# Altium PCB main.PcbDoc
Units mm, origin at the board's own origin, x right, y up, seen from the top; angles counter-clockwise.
Board outline 80 x 80 mm, 2 copper layers (Top, Bottom), stack 0 mm thick; 84 components, 75 nets, 337 pads, 197 vias.
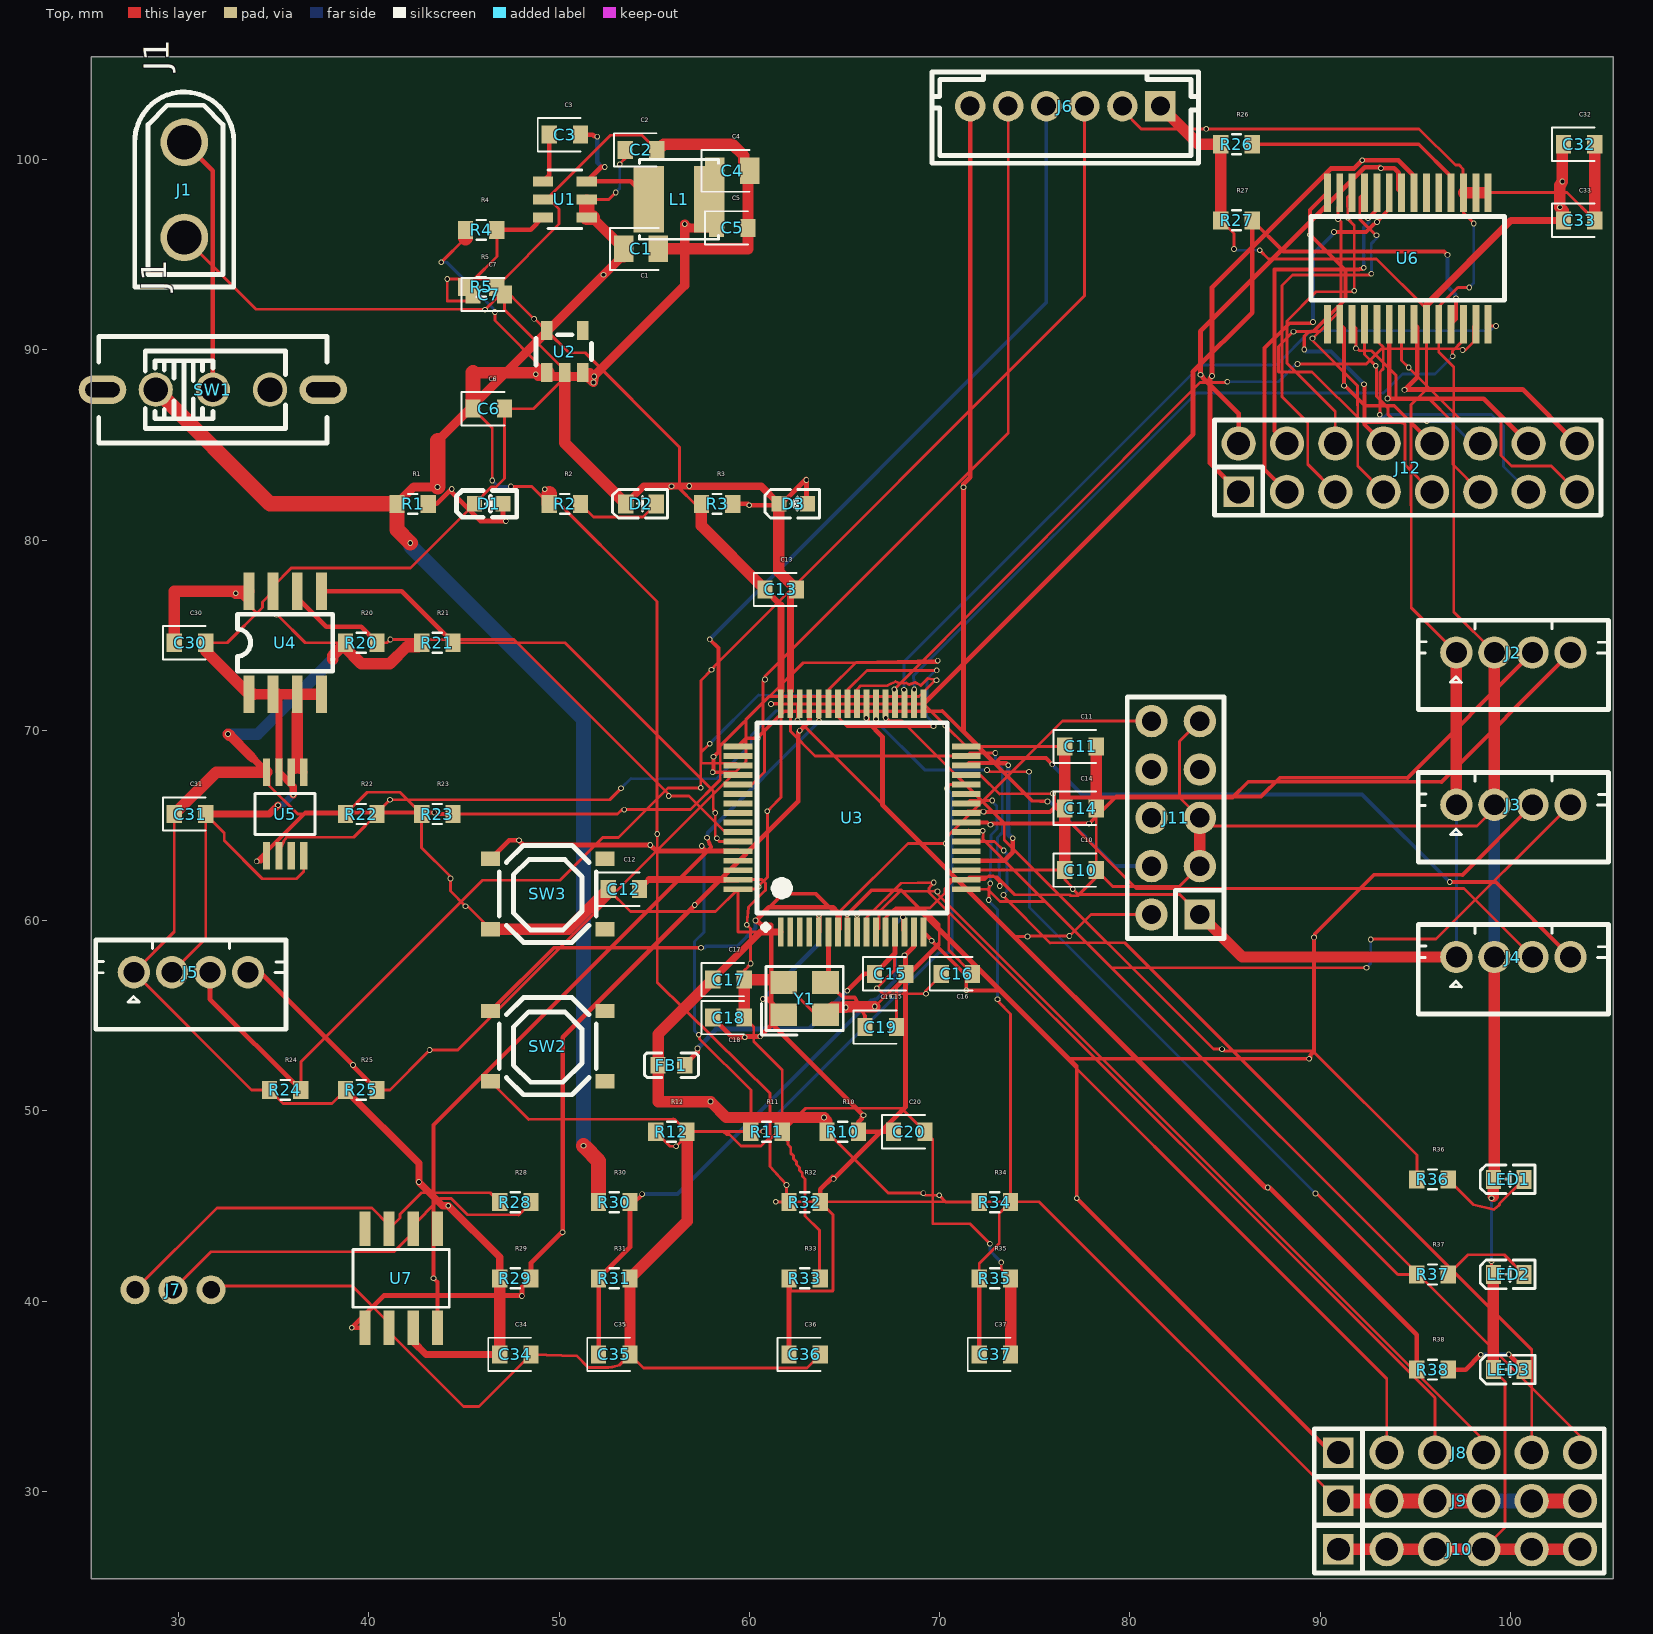
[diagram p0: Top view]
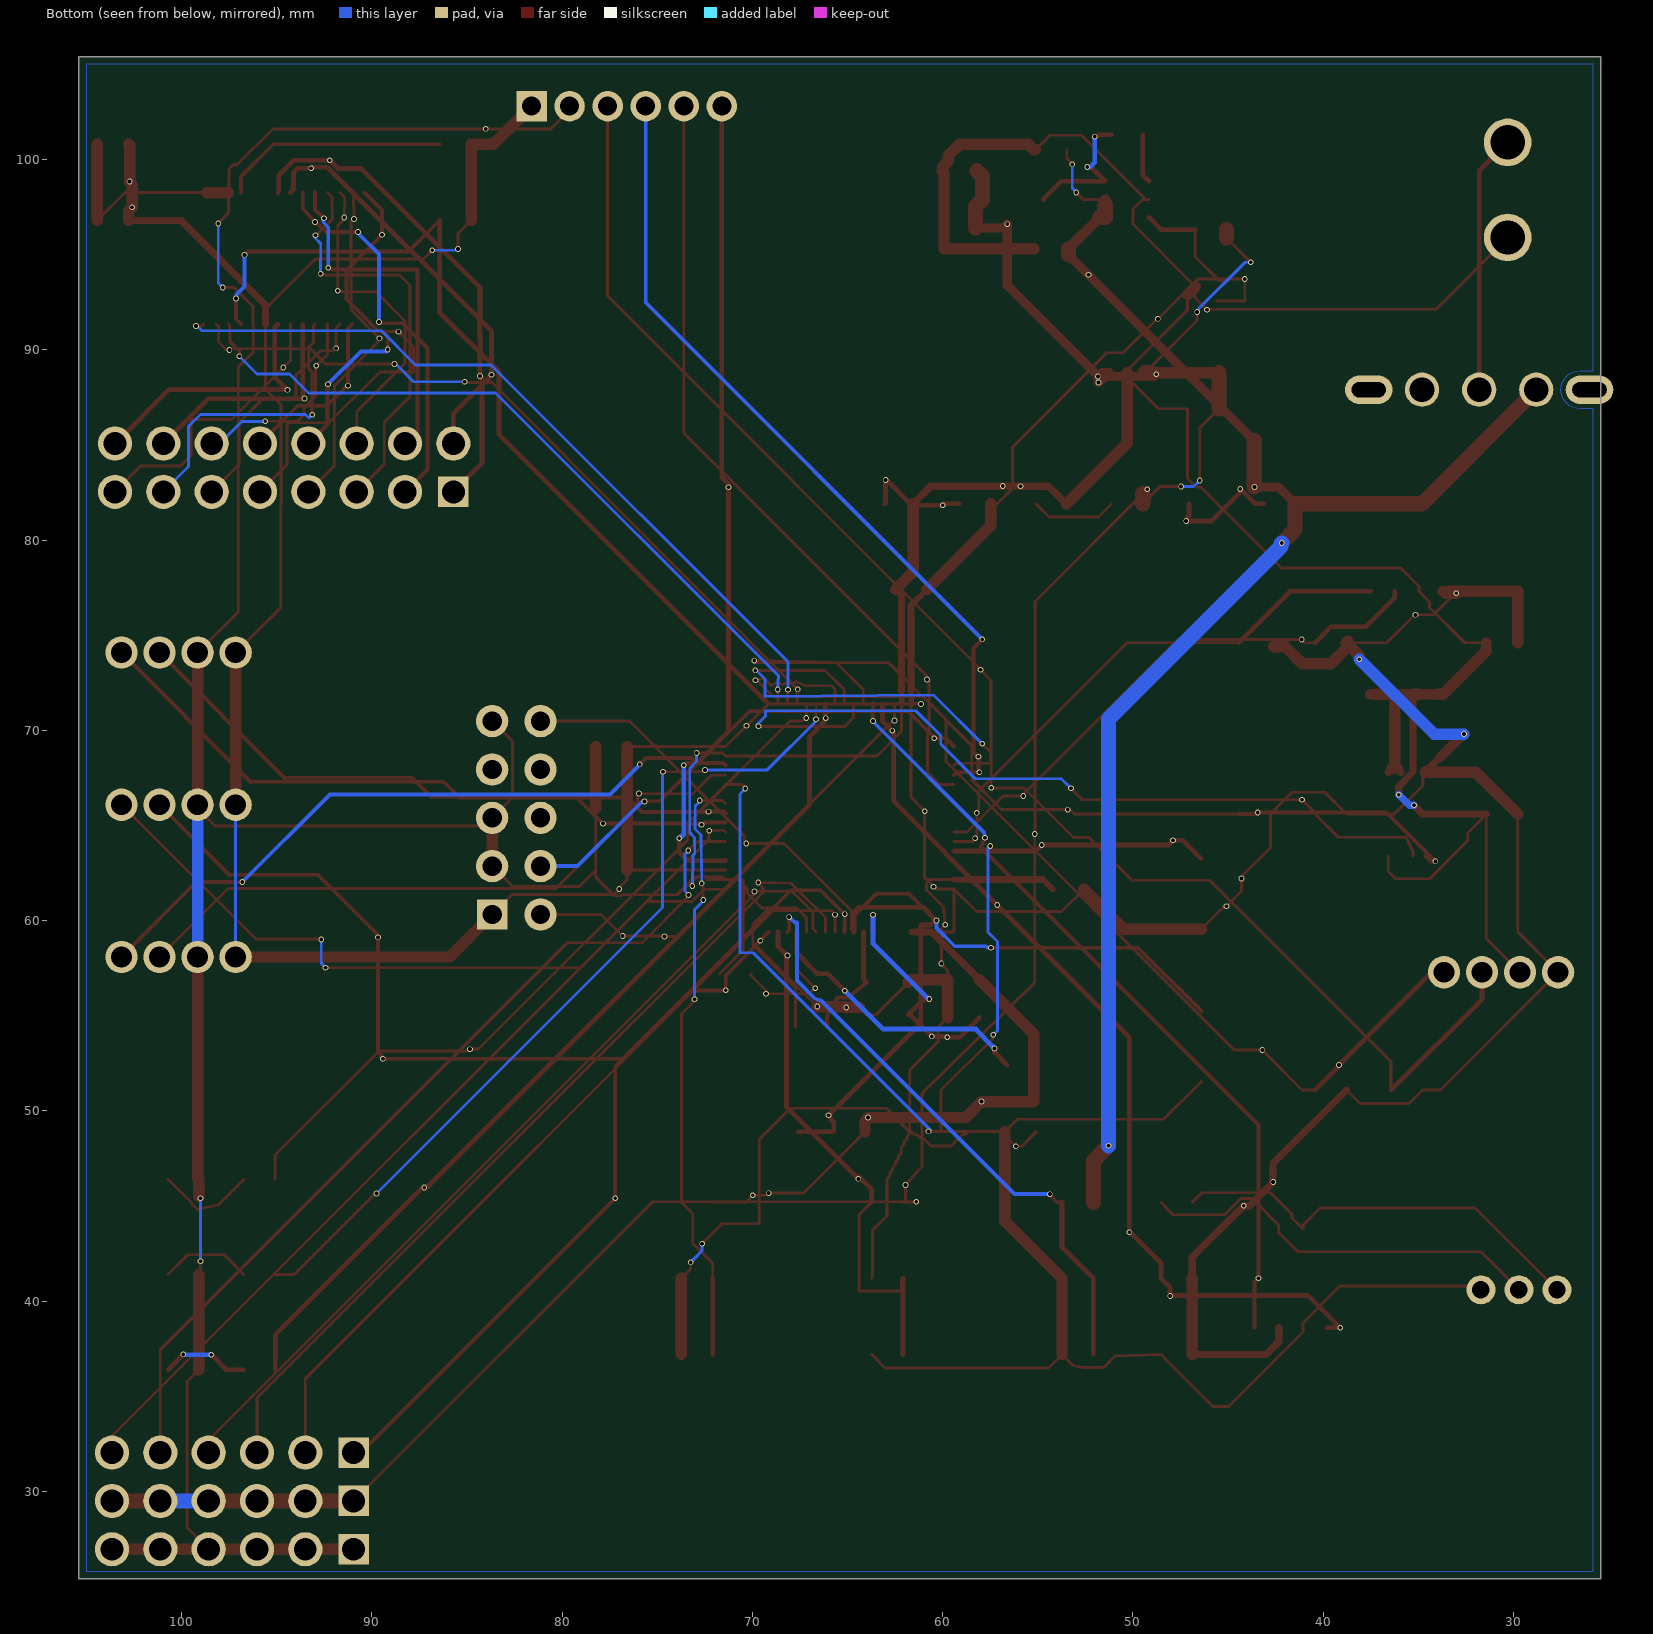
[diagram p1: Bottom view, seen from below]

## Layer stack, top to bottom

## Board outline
25.4,25.4 105.4,25.4 105.4,105.4 25.4,105.4

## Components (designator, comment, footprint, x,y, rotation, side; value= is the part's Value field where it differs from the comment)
C1 "" TSCIRCUIT-2.8500x1.4000mm 54.3,95.3 r0 top
C2 "" TSCIRCUIT-2.4500x0.9500mm 54.3,100.5 r0 top
C3 "" TSCIRCUIT-2.4500x0.9500mm 50.3,101.3 r0 top
C4 "" TSCIRCUIT-2.8500x1.4000mm 59.1,99.4 r0 top
C5 "" TSCIRCUIT-2.4500x0.9500mm 59.1,96.4 r0 top
C6 "" TSCIRCUIT-2.4500x0.9500mm 46.3,86.9 r0 top
C7 "" TSCIRCUIT-2.4500x0.9500mm 46.3,92.9 r0 top
C10 "" TSCIRCUIT-2.4500x0.9500mm 77.4,62.65 r0 top
C11 "" TSCIRCUIT-2.4500x0.9500mm 77.4,69.15 r0 top
C12 "" TSCIRCUIT-2.4500x0.9500mm 53.4,61.65 r0 top
C13 "" TSCIRCUIT-2.4500x0.9500mm 61.65,77.4 r0 top
C14 "" TSCIRCUIT-2.4500x0.9500mm 77.4,65.9 r0 top
C15 "" TSCIRCUIT-2.4500x0.9500mm 67.4,57.2 r0 top
C16 "" TSCIRCUIT-2.4500x0.9500mm 70.9,57.2 r0 top
C17 "" TSCIRCUIT-2.4500x0.9500mm 58.9,56.9 r0 top
C18 "" TSCIRCUIT-2.4500x0.9500mm 58.9,54.9 r0 top
C19 "" TSCIRCUIT-2.4500x0.9500mm 66.9,54.4 r0 top
C20 "" TSCIRCUIT-2.4500x0.9500mm 68.4,48.9 r0 top
C30 "" TSCIRCUIT-2.4500x0.9500mm 30.6,74.6 r0 top
C31 "" TSCIRCUIT-2.4500x0.9500mm 30.6,65.6 r0 top
C32 "" TSCIRCUIT-2.4500x0.9500mm 103.6,100.8 r0 top
C33 "" TSCIRCUIT-2.4500x0.9500mm 103.6,96.8 r0 top
C34 "" TSCIRCUIT-2.4500x0.9500mm 47.7,37.2 r0 top
C35 "" TSCIRCUIT-2.4500x0.9500mm 52.9,37.2 r0 top
C36 "" TSCIRCUIT-2.4500x0.9500mm 62.9,37.2 r0 top
C37 "" TSCIRCUIT-2.4500x0.9500mm 72.9,37.2 r0 top
D1 "" TSCIRCUIT-2.3001x0.8000mm 46.3,81.9 r0 top
D2 "" TSCIRCUIT-2.3989x1.0071mm 54.3,81.9 r0 top
D3 "" TSCIRCUIT-2.2980x0.8003mm 62.3,81.9 r0 top
FB1 "" TSCIRCUIT-2.1998x0.8640mm 55.9,52.4 r0 top
J1 "" TSCIRCUIT-2.5000x7.5000mm 30.3,98.4 r270 top
J2 "" TSCIRCUIT-7.7000x1.7000mm 100.15,74.085 r0 top
J3 "" TSCIRCUIT-7.7000x1.7000mm 100.15,66.085 r0 top
J4 "" TSCIRCUIT-7.7000x1.7000mm 100.15,58.085 r0 top
J5 "" TSCIRCUIT-7.7000x1.7000mm 30.65,57.285 r0 top
J6 "" TSCIRCUIT-11.6000x1.6000mm 76.6,102.8 r0 top
J7 "" TSCIRCUIT-5.5240x1.5240mm 29.71,40.595 r0 top
J8 "" TSCIRCUIT-14.5000x1.8000mm 97.3,32.04 r0 top
J9 "" TSCIRCUIT-14.5000x1.8000mm 97.3,29.5 r0 top
J10 "" TSCIRCUIT-14.5000x1.8000mm 97.3,26.96 r0 top
J11 "" TSCIRCUIT-4.2400x11.8600mm 82.4,65.4 r90 top
J12 "" TSCIRCUIT-19.5800x4.3400mm 94.6,83.8 r0 top
L1 "" TSCIRCUIT-4.7999x3.5000mm 56.3,97.9 r0 top
LED1 "" TSCIRCUIT-2.3989x1.0071mm 99.9,46.4 r0 top
LED2 "" TSCIRCUIT-2.3989x1.0071mm 99.9,41.4 r0 top
LED3 "" TSCIRCUIT-2.3989x1.0071mm 99.9,36.4 r0 top
R1 "" TSCIRCUIT-2.4500x0.9500mm 42.3,81.9 r0 top
R2 "" TSCIRCUIT-2.4500x0.9500mm 50.3,81.9 r0 top
R3 "" TSCIRCUIT-2.4500x0.9500mm 58.3,81.9 r0 top
R4 "" TSCIRCUIT-2.4500x0.9500mm 45.9,96.3 r0 top
R5 "" TSCIRCUIT-2.4500x0.9500mm 45.9,93.3 r0 top
R10 "" TSCIRCUIT-2.4500x0.9500mm 64.9,48.9 r0 top
R11 "" TSCIRCUIT-2.4500x0.9500mm 60.9,48.9 r0 top
R12 "" TSCIRCUIT-2.4500x0.9500mm 55.9,48.9 r0 top
R20 "" TSCIRCUIT-2.4500x0.9500mm 39.6,74.6 r0 top
R21 "" TSCIRCUIT-2.4500x0.9500mm 43.6,74.6 r0 top
R22 "" TSCIRCUIT-2.4500x0.9500mm 39.6,65.6 r0 top
R23 "" TSCIRCUIT-2.4500x0.9500mm 43.6,65.6 r0 top
R24 "" TSCIRCUIT-2.4500x0.9500mm 35.6,51.1 r0 top
R25 "" TSCIRCUIT-2.4500x0.9500mm 39.6,51.1 r0 top
R26 "" TSCIRCUIT-2.4500x0.9500mm 85.6,100.8 r0 top
R27 "" TSCIRCUIT-2.4500x0.9500mm 85.6,96.8 r0 top
R28 "" TSCIRCUIT-2.4500x0.9500mm 47.7,45.2 r0 top
R29 "" TSCIRCUIT-2.4500x0.9500mm 47.7,41.2 r0 top
R30 "" TSCIRCUIT-2.4500x0.9500mm 52.9,45.2 r0 top
R31 "" TSCIRCUIT-2.4500x0.9500mm 52.9,41.2 r0 top
R32 "" TSCIRCUIT-2.4500x0.9500mm 62.9,45.2 r0 top
R33 "" TSCIRCUIT-2.4500x0.9500mm 62.9,41.2 r0 top
R34 "" TSCIRCUIT-2.4500x0.9500mm 72.9,45.2 r0 top
R35 "" TSCIRCUIT-2.4500x0.9500mm 72.9,41.2 r0 top
R36 "" TSCIRCUIT-2.4500x0.9500mm 95.9,46.4 r0 top
R37 "" TSCIRCUIT-2.4500x0.9500mm 95.9,41.4 r0 top
R38 "" TSCIRCUIT-2.4500x0.9500mm 95.9,36.4 r0 top
SW1 "" TSCIRCUIT-14.1002x1.8000mm 31.8,87.9 r0 top
SW2 "" TSCIRCUIT-7x4.4498mm 49.4,53.4 r0 top
SW3 "" TSCIRCUIT-7x4.4498mm 49.4,61.4 r0 top
U1 "" TSCIRCUIT-3.3702x2.4319mm 50.3,97.9 r0 top
U2 "" TSCIRCUIT-2.4999x3.2001mm 50.3,89.9 r0 top
U3 "" TSCIRCUIT-13.5000x13.5000mm 65.4,65.4 r0 top
U4 "" TSCIRCUIT-4.3784x7.3604mm 35.6,74.6 r0 top
U5 "" TSCIRCUIT-2.3302x5.8498mm 35.6,65.6 r0 top
U6 "" TSCIRCUIT-8.8141x8.9258mm 94.6,94.8 r0 top
U7 "" TSCIRCUIT-4.3980x6.9999mm 41.7,41.2 r0 top
Y1 "" TSCIRCUIT-3.6001x2.9000mm 62.9,55.9 r0 top

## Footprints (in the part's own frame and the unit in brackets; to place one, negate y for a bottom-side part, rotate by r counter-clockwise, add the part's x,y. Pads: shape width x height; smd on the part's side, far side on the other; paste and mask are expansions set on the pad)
TSCIRCUIT-2.1998x0.8640mm [mm]
  rect 0.8x0.864 smd: 1(-0.7,0) 2(0.7,0)
  silkscreen extent -1.42,-0.65 1.42,0.65
TSCIRCUIT-2.2980x0.8003mm [mm]
  rect 0.8x0.8 smd: 1(-0.749,0) 2(0.749,0)
  silkscreen extent -1.49,-0.75 1.39,0.76
TSCIRCUIT-2.3001x0.8000mm [mm]
  rect 0.8x0.8 smd: 1(0.75,0) 2(-0.75,0)
  silkscreen extent -1.7,-0.7 1.47,0.7
TSCIRCUIT-2.3302x5.8498mm [mm]
  rect 0.38x1.45 smd: 1(-0.975,-2.2) 2(-0.325,-2.2) 3(0.325,-2.2) 4(0.975,-2.2) 5(0.975,2.2) 6(0.325,2.2) 7(-0.325,2.2) 8(-0.975,2.2)
  silkscreen extent -1.58,-1.07 1.58,1.07
TSCIRCUIT-2.3989x1.0071mm [mm]
  rect 0.8x1 smd: 1(-0.799,-0.004) 2(0.799,0.004)
  silkscreen extent -1.49,-0.75 1.39,0.76
TSCIRCUIT-2.4500x0.9500mm [mm]
  rect 0.8x0.95 smd: 1(-0.825,0) 2(0.825,0)
  silkscreen extent -1.43,-0.87 0.82,0.87
TSCIRCUIT-2.4999x3.2001mm [mm]
  rect 0.6x1 smd: 1(-0.95,-1.1) 2(0,-1.1) 3(0.95,-1.1) 4(0.95,1.1) 5(-0.95,1.1)
  silkscreen extent -1.52,-0.7 1.4,0.89
TSCIRCUIT-2.5000x7.5000mm [mm]
  round 2.5 hole 1.8: 1(-2.5,0) 2(2.5,0)
  silkscreen extent -5.14,-2.6 5.1,2.6
TSCIRCUIT-2.8500x1.4000mm [mm]
  rect 1.025x1.4 smd: 1(-0.913,0) 2(0.913,0)
  silkscreen extent -1.63,-1.1 0.91,1.1
TSCIRCUIT-3.3702x2.4319mm [mm]
  rect 1.072x0.532 smd: 1(-1.149,0.95) 2(-1.149,0) 3(-1.149,-0.95) 4(1.149,-0.95) 5(1.149,0) 6(1.149,0.95)
  silkscreen extent -0.89,-1.54 0.89,1.54
TSCIRCUIT-3.6001x2.9000mm [mm]
  rect 1.4x1.2 smd: 1(-1.1,-0.85) 2(1.1,-0.85) 3(1.1,0.85) 4(-1.1,0.85)
  silkscreen extent -2.26,-1.91 2.03,1.68
TSCIRCUIT-4.2400x11.8600mm [mm]
  rect 1.6x1.6 hole 1.02: 1(-5.08,-1.27)
  round 1.7 hole 1.02: 2(-5.08,1.27) 3(-2.54,-1.27) 4(-2.54,1.27) 5(0,-1.27) 6(0,1.27) 7(2.54,-1.27) 8(2.54,1.27) 9(5.08,-1.27) 10(5.08,1.27)
  silkscreen extent -6.35,-2.54 6.35,2.54
TSCIRCUIT-4.3784x7.3604mm [mil]
  rect 22.38x76.78 smd: 1(-75,-106.5) 2(-25,-106.5) 3(25,-106.5) 4(75,-106.5) 5(75,106.5) 6(25,106.5) 7(-25,106.5) 8(-75,106.5)
  silkscreen extent -98,-59 98,59
TSCIRCUIT-4.3980x6.9999mm [mm]
  rect 0.588x1.8 smd: 1(-1.905,-2.6) 2(-0.635,-2.6) 3(0.635,-2.6) 4(1.905,-2.6) 5(1.905,2.6) 6(0.635,2.6) 7(-0.635,2.6) 8(-1.905,2.6)
  silkscreen extent -2.53,-1.52 2.53,1.52
TSCIRCUIT-4.7999x3.5000mm [mm]
  rect 1.6x3.5 smd: 1(-1.6,0) 2(1.6,0)
  silkscreen extent -2.08,-2.1 2.08,2.1
TSCIRCUIT-5.5240x1.5240mm [mil]
  round 60 hole 36: 1(-78.74,0) 2(0,0) 3(78.74,0)
TSCIRCUIT-7.7000x1.7000mm [mm]
  round 1.7 hole 1.1: 1(-3,0) 2(-1,0) 3(1,0) 4(3,0)
  silkscreen extent -5,-3 5,1.7
TSCIRCUIT-7x4.4498mm [mm]
  rect 1x0.75 smd: 1(-3,1.85) 2(3,1.85) 3(-3,-1.85) 4(3,-1.85)
  silkscreen extent -2.55,-2.55 2.55,2.55
TSCIRCUIT-8.8141x8.9258mm [mm]
  rect 0.364x2.015 smd: 1(-4.225,-3.455) 2(-3.575,-3.455) 3(-2.925,-3.455) 4(-2.275,-3.455) 5(-1.625,-3.455) 6(-0.975,-3.455) 7(-0.325,-3.455) 8(0.325,-3.455) 9(0.975,-3.455) 10(1.625,-3.455) 11(2.275,-3.455) 12(2.925,-3.455) 13(3.575,-3.455) 14(4.225,-3.455) 15(4.225,3.455) 16(3.575,3.455) 17(2.925,3.455) 18(2.275,3.455) 19(1.625,3.455) 20(0.975,3.455) 21(0.325,3.455) 22(-0.325,3.455) 23(-0.975,3.455) 24(-1.625,3.455) 25(-2.275,3.455) 26(-2.925,3.455) 27(-3.575,3.455) 28(-4.225,3.455)
  silkscreen extent -5.08,-2.2 5.08,2.2
TSCIRCUIT-11.6000x1.6000mm [mm]
  rect 1.6x1.6 hole 1: 1(5,0)
  round 1.6 hole 1: 2(3,0) 3(1,0) 4(-1,0) 5(-3,0) 6(-5,0)
  silkscreen extent -7,-3 7,1.8
TSCIRCUIT-13.5000x13.5000mm [mm]
  rect 0.3x1.5 smd: 1(-3.75,-6) 2(-3.25,-6) 3(-2.75,-6) 4(-2.25,-6) 5(-1.75,-6) 6(-1.25,-6) 7(-0.75,-6) 8(-0.25,-6) 9(0.25,-6) 10(0.75,-6) 11(1.25,-6) 12(1.75,-6) 13(2.25,-6) 14(2.75,-6) 15(3.25,-6) 16(3.75,-6) 33(3.75,6) 34(3.25,6) 35(2.75,6) 36(2.25,6) 37(1.75,6) 38(1.25,6) 39(0.75,6) 40(0.25,6) 41(-0.25,6) 42(-0.75,6) 43(-1.25,6) 44(-1.75,6) 45(-2.25,6) 46(-2.75,6) 47(-3.25,6) 48(-3.75,6)
  rect 1.5x0.3 smd: 17(6,-3.75) 18(6,-3.25) 19(6,-2.75) 20(6,-2.25) 21(6,-1.75) 22(6,-1.25) 23(6,-0.75) 24(6,-0.25) 25(6,0.25) 26(6,0.75) 27(6,1.25) 28(6,1.75) 29(6,2.25) 30(6,2.75) 31(6,3.25) 32(6,3.75) 49(-6,3.75) 50(-6,3.25) 51(-6,2.75) 52(-6,2.25) 53(-6,1.75) 54(-6,1.25) 55(-6,0.75) 56(-6,0.25) 57(-6,-0.25) 58(-6,-0.75) 59(-6,-1.25) 60(-6,-1.75) 61(-6,-2.25) 62(-6,-2.75) 63(-6,-3.25) 64(-6,-3.75)
  silkscreen extent -5,-5.9 5,5
TSCIRCUIT-14.1002x1.8000mm [mm]
  round 1.8 hole 1.3: 1(-3,0) 2(0,0) 3(3,0)
  oval 2.5x1.5 hole 0.8 slot 1.8 at 0 deg: 4(5.8,0) 5(-5.8,0)
  silkscreen extent -6,-2.8 6,2.8
TSCIRCUIT-14.5000x1.8000mm [mm]
  rect 1.6x1.6 hole 1.2: 1(-6.35,0)
  round 1.8 hole 1.2: 2(-3.81,0) 3(-1.27,0) 4(1.27,0) 5(3.81,0) 6(6.35,0)
  silkscreen extent -7.62,-1.25 7.62,1.25
TSCIRCUIT-19.5800x4.3400mm [mm]
  rect 1.6x1.6 hole 1.2: 1(-8.89,-1.27)
  round 1.8 hole 1.2: 2(-8.89,1.27) 3(-6.35,-1.27) 4(-6.35,1.27) 5(-3.81,-1.27) 6(-3.81,1.27) 7(-1.27,-1.27) 8(-1.27,1.27) 9(1.27,-1.27) 10(1.27,1.27) 11(3.81,-1.27) 12(3.81,1.27) 13(6.35,-1.27) 14(6.35,1.27) 15(8.89,-1.27) 16(8.89,1.27)
  silkscreen extent -10.16,-2.5 10.16,2.5

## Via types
v1: diameter 0.3, hole 0.2, Top to Bottom, 197 vias

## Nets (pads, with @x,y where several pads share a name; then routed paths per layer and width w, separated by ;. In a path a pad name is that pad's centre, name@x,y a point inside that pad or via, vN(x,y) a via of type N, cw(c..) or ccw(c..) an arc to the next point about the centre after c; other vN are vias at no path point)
ADC_3V3: C37.1 R34.2 R35.1 U3.26 | length 32.1
  Top w0.15: U3.26 71.56,66.31 v1(72.757,66.308) ; R35.1 72.075,41.971 73.127,43.023 73.127,44.602 R34.2 73.725,55.094 73.113,55.706 73.113,55.784 v1(73.035,55.862) ; v1(72.581,61.081) 72.581,61.746 72.639,61.804 72.639,61.885 v1(72.655,61.954)
  Top w0.25: C37.1 R35.1
  Bottom w0.15: v1(72.581,61.081) 72.546,61.116 72.484,61.116 73.035,60.565 v1(73.035,55.862) ; v1(72.655,61.954) 72.69,64.503 73.006,64.806 72.997,66.021 72.805,66.21 72.805,66.26 v1(72.757,66.308)
ADC_5V: C36.1 R32.2 R33.1 U3.15 | length 28.4
  Top w0.15: R33.1 62.174,41.101 62.174,40.539 64.378,40.532 64.401,40.573 64.401,44.524 R32.2
  Top w0.25: C36.1 R33.1 ; R32.2 63.725,45.88 64.368,46.524 64.368,46.482 v1(64.425,46.425) 68.203,50.203 68.203,58.163 v1(68.151,58.163) 68.651,58.661 U3.15
ADC_12V: C35.1 R30.2 R31.1 U3.14 | length 31.9
  Top w0.2: R30.2 53.977,45.2 54.332,45.554 54.332,45.594 v1(54.362,45.624) ; v1(68.063,60.18) 68.055,59.495 U3.14
  Top w0.25: C35.1 R31.1 53.725,42.85 R30.2
  Bottom w0.2: v1(54.362,45.624) 56.22,45.624 66.392,55.804 66.699,55.891 67.652,56.843 67.652,59.901 67.77,59.901 68.096,60.227 v1(68.063,60.18)
BOOT0: R11.1 SW3.1 U3.60 | length 32.2
  Top w0.15: v1(57.336,53.995) 57.379,53.952 57.379,53.783 60.075,51.087 R11.1 ; v1(57.498,63.92) 57.806,63.65 U3.60
  Top w0.25: SW3.1 47.371,64.221 v1(47.885,64.221) 47.886,64.22 47.886,64.207 48.126,63.967 v1(54.786,63.967) 54.94,63.813 54.968,63.813 55.131,63.65 U3.60
  Bottom w0.15: v1(57.336,53.995) 57.12,54.21 57.114,58.903 57.606,59.387 57.606,63.774 57.606,63.85 v1(57.498,63.92)
CAN_RX: U3.44 U7.4 | length 41.4
  Top w0.2: U7.4 43.605,41.007 43.539,41.073 43.527,41.073 v1(43.4,41.2) 43.4,49.264 57.955,63.818 57.991,63.855 57.981,63.87 57.905,64.028 v1(57.774,64.355) ; U3.44 U3.44 v1(63.651,70.489)
  Bottom w0.2: v1(57.774,64.355) 57.814,64.626 63.613,70.425 63.613,70.451 v1(63.651,70.489)
CAN_TX: R29.2 U3.45 U7.1 | length 47.8
  Top w0.25: U7.1 39.295,38.6 v1(39.101,38.6) 40.791,40.29 47.938,40.29 48.019,40.29 v1(48.042,40.267) 48.042,40.717 R29.2 48.525,42.011 50.074,43.56 50.129,43.56 v1(50.184,43.615) 50.184,53.871 57.073,60.76 v1(57.13,60.817) 62.572,66.259 62.572,69.81 62.572,69.906 v1(62.647,69.981) 63.15,70.484 U3.45
CANH: J7.1 R28.1 U7.7 | length 22.6
  Top w0.15: J7.1 32.013,44.898 40.156,44.902 41.065,43.986 U7.7 41.628,44.363 41.628,44.566 42.759,45.696 42.905,45.696 46.379,45.696 R28.1
CANL: J7.2 R28.2 U7.6 | length 21.7
  Top w0.15: J7.2 31.71,42.595 41.32,42.591 42.336,43.612 U7.6 42.329,43.98 43.615,45.276 43.752,45.391 44.329,45.397 45.176,44.539 47.873,44.531 R28.2
D1_LIMIT: D1.1 R1.2 | length 6.2
  Top w0.25: R1.2 43.568,81.9 v1(44.352,82.684) 44.337,82.669 44.337,82.524 45.861,81 v1(47.2,81) 47.135,81.065 47.135,81.185 47.05,81.271 D1.1
D2_LIMIT: D2.2 R2.2 | length 4.6
  Top w0.15: R2.2 51.806,81.206 54.415,81.206 D2.2
D3_LIMIT: D3.2 R3.2 | length 5.8
  Top w0.25: R3.2 59.858,81.9 59.87,81.888 59.937,81.888 v1(59.994,81.83) 61.609,81.83 62.985,83.206 62.985,83.164 v1(62.993,83.156) 62.993,81.956 D3.2
FB: R4.2 R5.1 U1.3 | length 6.4
  Top w0.15: R5.1@44.963,93.633 45.1,93.565 45.295,93.565 45.487,93.654 46.725,94.892 R4.2
  Top w0.25: R4.2 48.501,96.3 U1.3
GND: C1.2 C2.2 C4.2 C5.2 C6.2 C7.2 C10.2 C11.2 C12.2 C13.2 C14.2 C15.2 C16.2 C17.2 C18.2 C19.2 C20.2 C30.2 C31.2 C32.2 C33.2 C34.2 C35.2 C36.2 C37.2 D1.2 D2.1 D3.1 J1.2 J2.2 J3.2 J4.2 J5.2 J6.2 J7.3 J10.1 J10.2 J10.3 J10.4 J10.5 J10.6 J11.3 J11.5 J11.9 LED1.1 LED2.1 LED3.1 R5.2 R11.2 R12.2 R31.2 R33.2 R35.2 SW2.3 U1.2 U2.2 U3.12 U3.18 U3.31 U3.47 U3.63 U4.1 U4.2 U4.3 U4.4 U4.7 U5.4 U5.5 U5.6 U5.7 U6.10 U6.15 U6.16 U6.17 U7.2 Y1.2 Y1.4 | length 508.3
  Top w0.15: J5.2 31.425,59.06 C31.2 31.425,65.575 32.4,64.6 32.4,64.2 34.4,62.2 36.2,62.2 36.575,62.575 U5.4 ; J1.2 34.074,92.126 46.078,92.126 v1(46.106,92.098) 46.725,92.717 R5.2 46.725,93.325 50,96.6 50,97.4 49.5,97.9 U1.2 49.326,97.9 52.694,101.268 54.357,101.268 C2.2 ; C30.2 32.555,74.6 34.404,76.449 34.404,76.744 U4.7 34.964,77.549 35.938,78.538 42.179,78.529 D1.2 46.435,82.785 46.683,82.785 47.125,83.227 C6.2 48.649,86.9 50.3,88.551 U2.2 50.311,88.911 47.125,92.097 C7.2 ; J7.3 31.912,40.797 39.127,40.797 41.065,38.859 U7.2 41.065,38.381 44.976,34.469 45.796,34.471 C34.2 50.936,37.113 51.529,36.52 51.85,36.52 52.1,36.52 52.35,36.52 52.6,36.52 52.793,36.543 53.155,36.63 C35.2 54.432,36.493 63.018,36.493 C36.2 ; SW2.3 48.398,49.555 55.996,49.567 56.073,49.552 R12.2 58.65,48.9 58.8,48.75 58.95,48.75 59.55,48.15 60.6,48.15 61.05,48.6 61.2,48.6 61.35,48.75 61.5,48.75 61.65,48.9 R11.2 ; U3.63 60.644,62.15 60.836,61.958 60.836,61.594 60.741,61.498 59.955,60.713 v1(59.858,59.78) 60.062,59.575 v1(60.062,57.744) 59.926,57.608 59.926,57.567 59.725,57.366 C17.2 ; C18.2 60.224,54.401 60.224,54.357 60.224,53.652 60.256,53.62 61.725,52.151 R11.2 ; Y1.4 63.5,55.05 Y1.2 Y1.2@64.384,55.434 ; U3.47 62.15,69.951 63.451,68.65 U3.31 71.566,68.81 v1(72.925,68.81) ; R33.2 63.725,41.275 63.675,41.325 63.675,43.725 62.925,44.475 62.925,46.425 62.775,46.575 62.775,46.725 62.625,46.875 62.625,47.025 62.475,47.175 62.475,47.325 62.325,47.475 62.325,47.625 62.175,47.775 62.175,48.075 62.025,48.225 62.025,48.375 61.875,48.525 61.875,48.675 61.725,48.825 R11.2 ; v1(65.063,55.434) v1@65.108,55.479 ; v1(66.588,55.479) 66.607,55.479 69.975,58.848 69.975,58.94 69.975,59.782 69.863,59.894 69.09,60.667 67.684,60.667 U3.12@67.15,60.133 ; C19.2 67.725,56.468 69.975,58.718 69.975,59.789 69.188,60.576 67.566,60.576 67.15,60.16 U3.12 ; C15.2 68.354,57.2 69.854,58.7 69.978,58.824 69.978,59.648 69.978,59.772 69.175,60.574 67.575,60.574 67.15,60.149 U3.12 ; C16.2 70.472,58.45 70.458,62.076 70.532,62.15 U3.18 ; v1(72.635,43.018) 72.625,43.028 71.583,44.07 69.631,44.07 69.631,48.494 C20.2 67.989,50.136 62.961,50.136 R11.2 ; v1(73.151,61.815) 73.151,62.022 72.823,62.349 72.567,62.349 72.368,62.15 U3.18 ; v1(73.236,42.037) 73.236,41.689 R35.2 ; C14.2 C10.2 ; J6.2 79.6,102.6 80.594,101.606 v1(84.004,101.606) 95.031,101.606 95.194,101.606 97.1,99.7 97.3,99.7 97.5,99.5 97.5,98.28 U6.17 97.525,97.197 98.014,96.708 98.014,96.687 v1(98.065,96.636) ; J11.3 82.61,61.8 79.075,61.8 C10.2 ; J11.9 82.61,69.42 82.61,66.46 J11.5 84.095,64.975 98.244,64.975 99.15,65.881 J3.2 ; v1(97.834,93.266) 97.229,93.266 96.244,92.282 96.244,91.364 U6.10 96.225,89.873 97.012,89.086 97.012,85.949 97.012,76.223 J2.2 ; J10.4 99.712,28.102 99.712,35.785 LED3.1 ; U6.15 102.97,98.255 C33.2 ; v1(98.993,42.095) 98.993,41.504 LED2.1 ; v1(99,45.404) v1@99.101,45.505 ; U3.12 U3.12@67.15,60.133 ; U3.12 U3.12@67.15,60.133 ; U3.12@67.15,60.133 67.681,60.664 69.488,60.664 70.272,61.447 70.272,61.689 70.733,62.15 U3.18 ; U3.18 71.575,62.303 72.997,62.303 73.944,61.356 76.831,61.356 76.884,61.303 77.255,61.303 78.225,62.273 C10.2
  Top w0.3: C12.2 54.725,62.15 ; U3.63@58.744,62.15 58.837,62.15 58.931,62.15 59.025,62.15 59.119,62.15 59.213,62.15 59.306,62.15 U3.63 ; U3.47 62.15,71.494 62.15,71.587 62.15,71.681 62.15,71.775 62.15,71.869 62.15,71.963 U3.47@62.15,72.056 ; C13.2@62.15,77.075 C13.2
  Top w0.364: U6.16@97.993,98.255 U6.16 ; U6.15@98.643,98.255 U6.15
  Top w0.375: C31.2 34.762,65.6 35.054,65.892 35.062,65.892 v1(35.229,66.059) ; U4.2 35.275,71.585 U5.7 36.024,67.051 v1(36.024,66.615) ; D2.1 54.431,82.827 v1(55.907,82.827) 55.909,82.829 56.087,82.829 56.09,82.833 v1(56.834,82.833) 56.841,82.826 56.935,82.826 60.625,82.826 D3.1 ; 54.725,62.15 58.65,62.15 U3.63@58.744,62.15 ; U3.47@62.15,72.056 62.15,72.15 C13.2@62.15,77.075
  Top w0.38: U5.6 36.115,67.99 ; U5.5@36.385,67.99 U5.5
  Top w0.568: C30.2@31.425,74.165 C30.2 ; U4.1@33.979,71.895 34.681,71.895 U4.2 ; U4.2@35.249,71.895 35.951,71.895 U4.3 ; U4.3@36.519,71.895 U4.3 ; U4.4@37.221,71.895 U4.4 ; U4.3@36.235,70.995 U4.3@36.235,71.145 ; U4.3@36.235,70.995 36.235,70.92 U4.3@36.235,70.995 ; U4.3@36.235,70.995 U4.3@36.235,71.145 ; U4.3@36.235,71.145 U4.3@36.235,71.295 ; U4.3@36.235,71.145 U4.3@36.235,71.295 ; U4.3@36.235,71.295 U4.3@36.235,71.445 ; U4.3@36.235,71.295 U4.3@36.235,71.445 ; U4.3@36.235,71.445 U4.3@36.235,71.595 ; U4.3@36.235,71.445 U4.3@36.235,71.595 ; U4.3@36.235,71.595 U4.3@36.235,71.745 ; U4.3@36.235,71.595 U4.3@36.235,71.745 ; U4.3@36.235,71.745 U4.3 ; U4.3@36.235,71.745 U4.3
  Top w0.579: 36.235,70.845 36.235,70.92 36.235,70.845
  Top w0.6: C30.2@31.425,74.165 31.465,74.125 33.411,72.179 U4.1 U4.1@33.979,71.895 ; U4.2 U4.2@35.249,71.895 ; 36.115,67.99 36.235,68.11 36.235,70.695 ; U5.5@36.385,67.99 36.235,68.14 36.235,70.695 ; U4.3@36.519,71.895 U4.4@37.221,71.895 ; R5.2 C7.2 ; U2.2 50.3,88.65 50.3,88.5 50.3,88.35 50.3,88.3 50.3,88.2 50.3,88.05 50.3,87.9 50.3,87.75 50.3,85.097 D2.1 ; C35.2 R31.2 56.725,44.2 R12.2 ; C2.2 55.2,100.5 55.5,100.8 59.1,100.8 59.7,100.2 59.7,99.9 60,99.6 60,99.387 C4.2 59.925,99.312 C5.2 59.925,95.3 C1.2 ; C18.2 C17.2 61.65,56.9 Y1.4 ; D3.1 61.551,78.324 C13.2 ; Y1.2@64.384,55.434 v1(65.063,55.434) ; v1@65.108,55.479 v1(66.588,55.479) ; C37.2 R35.2 ; C14.2 C11.2 ; J11.3 J11.5 ; J10.1 J10.2 J10.3 J10.4 J10.5 J10.6 ; U6.17 97.707,98.255 U6.16@97.993,98.255 ; U6.16 98.357,98.255 U6.15@98.643,98.255 ; LED3.1 LED2.1 ; v1@99.101,45.505 LED1.1 LED1.1@99.149,46.445 ; LED1.1@99.15,46.445 J4.2 ; J3.2 J2.2 ; C33.2 C32.2 ; 36.235,70.695 36.235,70.845 36.235,70.695
  Bottom w0.15: v1(72.635,43.018) 72.635,42.649 73.08,42.204 73.08,42.193 v1(73.236,42.037) ; v1(72.925,68.81) 72.925,68.353 73.283,67.995 73.283,64.614 73.03,64.359 73.026,63.52 73.12,63.431 v1(73.151,61.815) ; v1(97.834,93.266) 97.975,93.407 97.975,93.424 98.065,93.514 v1(98.065,96.636) ; v1(98.993,42.095) 98.994,42.154 99,42.16 v1(99,45.404)
  Bottom w0.375: v1(35.229,66.059) 35.468,66.059 36.004,66.595 v1(36.024,66.615)
  Bottom w0.6: J4.2 J3.2
GPIO_GPA0: J12.1 U6.21 | length 26
  Top w0.25: J12.1 84.207,84.033 84.207,88.407 84.207,88.503 v1(84.313,88.617) 84.311,93.271 90.562,99.52 91.77,99.519 92.152,99.902 92.159,99.902 v1(92.207,99.958) 94.105,99.953 94.885,99.175 94.883,98.297 U6.21
GPIO_GPA1: J12.2 U6.22 | length 21.9
  Top w0.25: J12.2 85.71,86.643 83.817,88.536 83.817,88.576 v1(83.705,88.688) 83.702,90.958 92.346,99.594 93.094,99.6 93.121,99.6 v1(93.185,99.536) 93.876,99.536 94.116,99.296 94.116,98.414 U6.22
GPIO_GPA2: J12.3 U6.23 | length 20.6
  Top w0.2: J12.3 87.072,83.708 87.072,90.085 88.377,91.39 89.531,91.39 89.553,91.39 v1(89.617,91.458) ; v1(90.716,96.184) 92.402,96.184 92.799,96.582 ; 92.8,96.582 v1(92.981,96.718) 93.625,97.407 U6.23
  Bottom w0.2: v1(89.617,91.458) 89.619,95.028 90.628,96.037 90.628,96.096 v1(90.716,96.184)
GPIO_GPA3: J12.4 U6.24 | length 18.4
  Top w0.2: J12.4 87.589,85.731 87.589,94.215 92.047,94.216 92.076,94.243 92.22,94.243 v1(92.284,94.313) ; v1(92.504,96.912) 92.975,97.337 U6.24
  Bottom w0.2: v1(92.284,94.313) 92.287,96.436 92.551,96.699 92.551,96.863 v1(92.504,96.912)
GPIO_GPA4: J12.5 U6.25 | length 21.8
  Top w0.15: J12.5 89.34,83.984 89.34,86.177 87.982,87.531 87.982,93.367 88.544,93.926 92.483,93.926 92.617,93.928 v1(92.685,93.99) ; U6.25 92.086,98.016 92.077,96.856 92.93,96.015 v1(92.953,96.018)
  Bottom w0.15: v1(92.685,93.99) 92.682,95.569 92.98,95.867 92.98,95.991 v1(92.953,96.018)
GPIO_GPA5: J12.6 U6.26 | length 17.1
  Top w0.15: J12.6 90.79,86.749 88.265,89.274 88.249,89.289 88.247,91.517 89.78,93.047 91.594,93.047 91.73,93.047 v1(91.784,93.101) 91.784,96.537 91.442,96.879 91.442,96.923 v1(91.442,96.952) 91.417,97.997 U6.26
GPIO_GPA6: J12.7 U6.27 | length 18
  Top w0.15: U6.27 90.96,98.19 v1(90.935,96.867) 91.093,96.738 91.093,96.725 91.093,92.097 v1(89.594,90.596) 89.594,90.482 91.965,88.102 91.972,85.967 91.972,83.888 J12.7
GPIO_GPA7: J12.8 U6.28 | length 17.9
  Top w0.2: v1(89.154,90.011) 89.154,90.712 89.364,90.923 89.657,90.981 91.329,92.654 91.329,93.217 91.329,94.176 89.528,95.977 v1(89.461,96.044) 89.461,97.341 U6.28 ; v1(92.294,88.19) 92.323,88.152 92.323,86.077 J12.8
  Bottom w0.2: v1(89.154,90.011) 89.253,89.912 90.563,89.912 v1(92.294,88.19)
GPIO_GPB0: J12.9 U6.1 | length 16.3
  Top w0.15: U6.1 89.981,90.951 v1(88.588,90.951) 88.556,90.924 87.802,90.17 87.802,88.825 89.563,88.825 92.29,86.131 92.491,86.181 92.7,86.16 92.9,86.16 93.1,86.16 93.3,86.16 93.5,86.16 93.7,86.16 93.9,86.16 94.244,86.169 94.444,86.09 94.446,85.94 94.446,83.954 J12.9
GPIO_GPB1: J12.10 U6.2 | length 9.2
  Top w0.2: U6.2 91.249,91.121 v1(91.249,88.112) 91.304,88.057 91.352,88.057 92.357,87.053 92.435,87.053 93.89,87.055 J12.10
GPIO_GPB2: J12.11 U6.3 | length 13
  Top w0.15: U6.3 91.87,91.15 v1(91.87,90.07) 91.907,90.033 91.98,90.033 92.07,89.943 92.692,89.943 93.978,88.657 93.978,87.477 95.673,87.477 96.967,86.182 96.967,83.973 J12.11
GPIO_GPB3: J12.12 U6.4 | length 10.7
  Top w0.15: U6.4 92.325,89.753 v1(92.919,89.159) 92.96,89.118 92.96,89.109 92.96,87.537 93.257,87.237 93.55,86.946 93.55,86.611 93.917,86.244 v1(95.6,86.244)
  Bottom w0.15: v1(95.6,86.244) 95.614,86.23 95.621,86.23 96.826,86.23 97.048,86.007 97.986,85.07 J12.12
GPIO_GPB4: J12.13 U6.5 | length 15.9
  Top w0.15: U6.5 93.065,91.255 93.065,90.376 93.307,90.134 93.307,89.003 93.13,88.826 v1(93.13,86.578)
  Bottom w0.15: v1(93.13,86.578) 93.299,86.409 93.494,86.603 95.383,86.603 99.003,86.603 99.625,85.981 99.625,83.855 J12.13
GPIO_GPB5: J12.14 U6.6 | length 12.3
  Top w0.25: U6.6 93.625,87.529 v1(93.535,87.439) 93.546,87.426 93.676,87.426 98.594,87.426 J12.14
GPIO_GPB6: J12.15 U6.7 | length 15.1
  Top w0.15: U6.7 94.275,89.433 v1(94.647,89.064) 94.688,89.019 97.378,86.33 99.5,86.33 99.5,84.432 100.05,83.882 102.138,83.882 J12.15
GPIO_GPB7: J12.16 U6.8 | length 14.1
  Top w0.25: U6.8 95.101,91.169 95.101,88.56 v1(94.43,87.889) 94.456,87.915 100.645,87.915 J12.16
GPIO_LED1: R36.1 U3.37 | length 40
  Top w0.15: U3.37 67.147,71.397 v1(67.167,70.641) 67.225,70.568 67.311,70.568 67.394,70.485 68.025,70.485 73.392,65.118 73.392,64.241 84.387,53.246 v1(84.833,53.243) 84.868,53.214 84.893,53.214 84.971,53.136 89.61,53.136 95.075,47.672 R36.1
GPIO_LED2: R37.1 U3.38 | length 45.6
  Top w0.15: U3.38 66.637,71.387 v1(66.655,70.583) ; v1(72.481,67.913) 72.525,67.922 72.628,67.819 v1(74.694,67.819) ; v1(89.75,45.652) 89.759,45.643 89.833,45.643 94.075,41.4 R37.1
  Bottom w0.15: v1(66.655,70.583) 66.694,70.532 66.694,70.44 69.213,67.922 v1(72.481,67.913) ; v1(74.694,67.819) 74.72,67.793 74.72,67.675 74.72,60.682 v1(89.75,45.652)
GPIO_LED3: R38.1 U3.39 | length 47.1
  Top w0.25: U3.39 66.18,71.37 v1(66.143,70.64) 66.213,70.61 66.213,70.443 66.992,69.664 66.992,66.097 87.121,45.968 v1(87.237,45.968) 87.265,45.94 87.362,45.94 95.075,38.227 R38.1
HSE_IN: C18.1 U3.5 Y1.1 | length 12.7
  Top w0.25: C18.1 59.104,53.871 v1(59.757,53.871) 59.771,53.885 59.834,53.885 59.862,53.913 v1(60.572,53.913) 60.578,53.919 61.709,55.05 Y1.1 60.972,55.878 v1(60.699,55.878) ; U3.5 63.65,60.15 63.65,60.3 v1(63.651,60.301)
  Bottom w0.25: v1(60.699,55.878) 60.705,55.884 60.748,55.884 63.651,58.787 v1(63.651,60.301)
HSE_OUT: C19.1 U3.6 Y1.3 | length 6.2
  Top w0.2: Y1.3 64.96,55.963 65.526,55.949 66.075,54.983 C19.1
  Top w0.25: Y1.3 64.15,56.9 U3.6
I2C1_SCL: R20.2 U3.58 U4.6 | length 28.8
  Top w0.15: R20.2 40.957,74.6 v1@41.121,74.764 ; v1@41.122,74.764 v1(41.131,74.773) 47.62,74.773 55.718,66.675 55.718,66.593 v1(55.765,66.546) 56.824,66.549 58.723,64.65 U3.58
  Top w0.25: U4.6 36.235,76.965 37.762,75.438 39.587,75.438 R20.2
I2C1_SDA: R21.2 U3.59 U4.5 | length 28.7
  Top w0.15: R21.2 50.311,74.6 58.1,66.811 58.1,65.857 58.132,65.825 58.132,65.729 v1(58.201,65.66) 58.201,64.447 58.226,64.422 58.226,64.334 v1(58.288,64.326) 58.41,64.15 U3.59
  Top w0.25: U4.5 41.72,77.305 R21.2
I2C2_SCL: R22.2 U3.42 U5.2 | length 44.8
  Top w0.15: U5.2 35.275,63.652 35.381,63.827 35.509,64.14 35.693,64.386 39.202,64.377 R22.2 40.425,65.669 41.084,66.327 41.089,66.327 v1(41.113,66.351) 52.658,66.351 53.156,66.849 53.156,66.855 v1(53.251,66.95) ; U3.42 64.673,71.377 64.673,70.664 65.13,70.208 v1(69.677,70.208)
  Bottom w0.15: v1(53.251,66.95) 53.768,67.466 58.285,67.454 60.096,69.278 60.092,69.718 61.406,71.024 69.297,71.024 69.297,70.755 69.76,70.291 v1(69.677,70.208)
I2C2_SDA: R23.2 U3.43 U5.1 | length 49.1
  Top w0.15: R23.2 53.075,65.6 53.322,65.848 53.406,65.848 v1(53.423,65.831) 56.894,65.831 58.468,67.405 58.468,69.188 61.05,71.774 62.832,73.551 69.807,73.551 69.858,73.551 v1(69.896,73.662) 65.602,73.568 64.171,72.137 64.171,71.421 U3.43
  Top w0.2: U5.1 34.336,63.111 v1(34.101,63.111) 34.173,63.183 36.665,65.675 v1(43.44,65.675) 43.42,65.695 43.464,65.695 43.559,65.6 R23.2
I2C3_SCL: J5.3 R24.2 U3.41 | length 59.1
  Top w0.15: R24.2 36.424,52.562 45.974,62.12 50.04,62.115 52.295,64.369 53.111,64.369 55.712,66.975 57.214,66.972 57.441,66.972 v1(57.444,66.975) 57.444,68.828 57.898,69.282 v1(57.912,69.296) ; U3.41 65.171,71.421 65.171,72.135 66.183,73.148 v1(69.847,73.149)
  Top w0.25: J5.3 31.65,55.875 R24.2
  Bottom w0.15: v1(57.912,69.296) 60.482,71.852 69.325,71.777 69.325,72.687 69.626,72.988 69.786,73.148 v1(69.847,73.149)
I2C3_SDA: J5.4 R25.2 U3.40 | length 54.5
  Top w0.15: R25.2 41.103,51.1 43.108,53.105 43.108,53.113 v1(43.193,53.198) 44.669,53.198 59.828,68.356 59.828,70.593 61.009,71.774 68.914,71.774 69.858,72.719 v1(69.833,72.635) 69.37,72.723 69.007,72.36 68.703,72.512 68.4,72.407 68.261,72.478 67.924,72.455 67.684,72.559 67.435,72.445 67.231,72.341 65.838,72.34 65.651,72.151 65.651,71.401 U3.40
  Top w0.25: J5.4 34.285,57.285 39.127,52.443 v1(39.165,52.405) 39.165,52.36 R25.2
LED1_LIMIT: LED1.2 R36.2 | length 5.2
  Top w0.15: R36.2 98.058,45.065 99.122,44.82 99.423,45.064 99.423,45.127 LED1.2
LED2_LIMIT: LED2.2 R37.2 | length 4.8
  Top w0.15: R37.2 97.763,42.438 99.545,42.438 99.665,42.438 LED2.2
LED3_LIMIT: LED3.2 R38.2 | length 4.6
  Top w0.25: R38.2 97.634,36.4 98.405,37.171 98.415,37.171 v1(98.429,37.185) ; v1(99.902,37.203) 99.902,37.201 LED3.2
  Bottom w0.25: v1(98.429,37.185) 99.679,37.185 99.884,37.185 v1(99.902,37.203)
MCP_RESET: R26.2 U6.18 | length 12
  Top w0.2: R26.2 95.172,100.8 96.876,99.098 U6.18
NRST: C20.1 J11.10 R10.2 SW2.1 U3.7 | length 65.7
  Top w0.15: U3.7 64.79,59.54 64.79,60.512 68.329,64.051 v1(70.314,64.051) 70.423,64.154 70.423,64.205 70.423,64.452 72.687,66.719 76.451,70.48 J11.10
  Top w0.2: SW2.1 49.724,58.574 v1(57.454,58.574) ; v1(60.323,60) 60.336,59.987 61.752,61.404 63.495,61.404 64.65,60.25 U3.7
  Top w0.25: U3.7 64.65,60.448 64.395,60.703 61.027,60.703 v1(60.323,60) 60.401,59.922 60.477,59.922 60.638,59.761 61.147,59.761 61.147,54.614 v1(65.992,49.769) 65.9,49.677 65.9,49.577 65.725,49.402 R10.2 C20.1
  Bottom w0.2: v1(57.454,58.574) 57.646,58.574 57.722,58.65 59.364,58.65 60.323,59.609 v1(60.323,60)
PWM1: J8.1 U3.8 | length 43.6
  Top w0.2: U3.8 U3.8 v1(65.144,60.339) 65.189,60.377 66.41,61.598 67.977,61.598 77.203,52.372 v1(77.203,45.405) 77.233,45.375 77.237,45.375 90.572,32.04 J8.1
PWM2: J8.2 U3.9 | length 42.9
  Top w0.15: U3.9 65.651,59.401 v1(65.658,60.313) 65.696,60.358 65.696,60.38 65.811,60.494 65.811,60.518 68.898,60.521 69.013,60.401 93.49,35.924 J8.2
PWM3: J8.3 U3.10 | length 46.1
  Top w0.15: U3.10 66.144,60.155 67.957,61.964 v1(69.69,62.002) 69.428,61.681 69.417,61.51 96.03,34.918 J8.3
PWM4: J8.4 U3.11 | length 46.3
  Top w0.15: U3.11 66.806,59.573 66.812,60.447 67.911,61.539 v1(69.883,61.525) 69.862,61.55 69.726,61.55 98.57,32.706 J8.4
PWM5: J8.5 U3.22 | length 47.8
  Top w0.15: U3.22 72.879,64.15 v1(73.367,63.679) ; v1(73.352,61.341) 73.342,61.356 73.342,61.286 75.799,58.83 79.725,58.832 101.111,37.443 J8.5
  Bottom w0.15: v1(73.352,61.341) 73.541,61.555 73.541,63.53 73.499,63.53 v1(73.367,63.679)
PWM6: J8.6 U3.23 | length 46.6
  Top w0.15: U3.23 71.505,64.755 v1(72.26,64.722) 72.27,64.721 72.287,64.704 72.282,64.277 103.65,32.919 J8.6
R12_BOOT1: R12.1 U3.28 | length 30.2
  Top w0.15: R12.1 55.833,48.142 v1(56.147,48.142) 56.213,48.208 56.225,48.208 56.938,48.921 v1(60.74,48.921) ; v1(70.366,66.94) 70.451,67.025 70.451,67.058 70.543,67.15 U3.28
  Bottom w0.15: v1@60.621,48.98 v1(60.74,48.921) ; v1@60.622,48.98 69.951,58.309 70.652,58.309 70.654,66.656 v1(70.366,66.94)
SPI2_CS: R27.2 U3.33 U6.11 | length 47.5
  Top w0.2: R27.2 88.06,95.165 96.497,95.165 96.505,95.165 v1(96.686,94.984) ; U6.11 97.127,91.6 v1(97.129,92.687)
  Top w0.25: U3.33 83.311,85.558 83.307,88.843 86.425,91.956 R27.2
  Bottom w0.2: v1(96.686,94.984) 96.686,93.327 97.104,92.909 97.104,92.717 v1(97.129,92.687)
SPI2_MISO: U3.35 U6.14 | length 41.2
  Top w0.15: v1(68.124,72.128) 68.142,72.168 68.15,72.146 68.15,71.9 U3.35 ; U6.14 98.921,91.249 v1(99.233,91.249)
  Bottom w0.15: v1(68.124,72.128) 68.129,73.6 83.731,89.202 87.693,89.202 89.486,90.995 98.913,90.995 99.2,91.282 v1(99.233,91.249)
SPI2_MOSI: U3.36 U6.13 | length 39.9
  Top w0.15: U3.36 67.65,71.9 67.65,72.15 67.65,72.155 v1(67.608,72.151) 83.687,88.277 84.976,88.277 85.084,88.282 v1(85.117,88.315) ; v1(88.8,89.248) 92.412,89.248 93.214,90.05 97.372,90.05 97.434,89.988 97.47,89.988 v1(97.481,89.989) 97.624,89.985 98.052,90.413 98.043,91.213 U6.13
  Bottom w0.15: v1(85.117,88.315) 87.801,88.315 88.73,89.244 88.796,89.244 v1(88.8,89.248)
SPI2_SCK: U3.34 U6.12 | length 38.7
  Top w0.15: U3.34 68.65,71.9 68.65,72.15 68.65,72.155 v1(68.666,72.139) ; v1(96.956,89.657) 96.954,89.941 97.457,90.446 97.46,91.28 U6.12
  Bottom w0.15: v1(68.666,72.139) 68.616,72.864 83.495,87.719 93.32,87.718 94.327,88.723 96.024,88.725 96.941,89.642 v1(96.956,89.657)
SPI3_CS: J6.6 U3.20 | length 43.4
  Top w0.25: U3.20 73.383,63.15 73.644,63.405 73.835,63.602 v1(73.835,64.325) ; J6.6 71.6,83.292 71.252,82.944 v1(71.253,82.776) v1(71.253,82.776) 71.253,69.918 72.905,68.267 73.493,68.267 v1(73.598,68.165)
  Bottom w0.25: v1(73.598,68.165) 73.598,64.515 73.664,64.446 73.714,64.446 v1(73.835,64.325)
SPI3_MISO: J6.4 U3.52 | length 44
  Top w0.2: v1(57.911,74.779) 58.376,74.317 58.373,68.971 58.372,68.857 58.277,68.761 58.274,68.761 v1(58.113,68.605) 58.113,67.906 58.075,67.868 58.075,67.808 v1(58.066,67.794) 59.251,67.775 U3.52
  Bottom w0.2: v1(57.911,74.779) 57.977,74.844 57.977,74.85 75.6,92.473 J6.4
SPI3_MOSI: J6.5 U3.53 | length 42
  Top w0.15: U3.53 60.138,67.15 60.792,67.804 60.792,69.906 60.719,69.979 60.719,72.575 v1(60.816,72.672) 60.826,72.682 60.826,72.841 73.6,85.616 J6.5
SPI3_SCK: J6.3 U3.51 | length 44.9
  Top w0.15: U3.51 59.283,68.265 57.45,68.264 57.45,72.614 v1(58.011,73.18) 58.144,73.308 58.144,73.359 77.6,92.815 J6.3
SW: C3.2 L1.1 U1.6 | length 7.7
  Top w0.25: C3.2 51.762,101.3 51.842,101.22 51.98,101.22 v1(52,101.2) ; v1(52.4,99.6) 52.199,99.6 U1.6 53.75,98.85 L1.1
  Bottom w0.25: v1(52,101.2) 52,99.843 52.243,99.6 v1(52.4,99.6)
SWCLK: J11.4 U3.49 | length 25.9
  Top w0.2: U3.49 59.839,69.589 v1(60.441,69.585) 60.421,69.605 60.419,69.605 61.812,71.004 70.137,71.007 74.843,66.293 v1(75.661,66.256)
  Bottom w0.2: v1(75.661,66.256) 75.726,66.253 75.786,66.253 79.18,62.86 J11.4
SWDIO: J11.2 U3.46 | length 24.7
  Top w0.15: U3.46 62.52,71.27 v1(62.528,70.515) 62.573,70.466 62.596,70.466 62.64,70.469 67.173,65.929 73.942,59.16 v1(74.616,59.16) 74.643,59.187 74.815,59.187 v1(76.815,59.187) 76.84,59.212 77.948,60.32 J11.2
U1_BS: C3.1 U1.1 | length 2.6
  Top w0.25: U1.1 49.475,99.174 C3.1
UART1_RX: J2.4 U3.25 | length 35.3
  Top w0.2: U3.25 71.475,65.725 v1(72.3,65.725) 72.351,65.674 72.387,65.674 72.416,65.702 72.624,65.702 75.797,65.702 76.558,66.465 85.385,66.465 86.214,67.292 96.365,67.285 J2.4
UART1_TX: J2.3 U3.24 | length 33.5
  Top w0.2: U3.24 72.491,65.15 v1(72.664,65.04) 72.723,65.094 72.788,65.094 v1(77.847,65.094) 77.868,65.115 79.277,66.524 79.283,66.524 86.891,66.524 87.875,67.507 94.58,67.499 J2.3
UART2_RX: J3.4 U3.17 | length 37.7
  Top w0.15: U3.17 72.518,61.643 72.807,61.364 73.169,61.003 73.372,61.001 75.562,61.003 75.956,60.608 79.036,57.529 v1(92.426,57.521) ; v1(92.654,59.009) 92.67,59.025 96.09,59.025 J3.4
  Bottom w0.15: v1(92.426,57.521) 92.478,57.581 92.478,57.583 92.654,57.759 v1(92.654,59.009)
UART2_TX: J3.3 U3.16 | length 44.5
  Top w0.2: U3.16 69.574,58.976 v1(69.574,58.944) 69.652,58.866 69.652,58.857 71.397,57.112 v1(71.397,56.335) 71.404,56.342 71.42,56.326 73.155,56.326 76.743,52.738 v1(89.414,52.738) 89.484,52.808 89.484,52.942 89.665,53.124 v1(89.665,59.116) 89.711,59.162 89.711,59.301 92.816,62.406 92.924,62.406 97.478,62.399 J3.3
UART3_RX: J4.4 U3.30 | length 36.3
  Top w0.2: U3.30 71.523,68.276 72.917,68.279 73.184,68.541 73.553,68.541 75.578,68.541 v1(75.911,68.208) ; v1(96.806,62.024) 99.224,62.025 J4.4
  Bottom w0.2: v1(75.911,68.208) 76.06,68.059 76.06,68.046 77.478,66.629 82.719,66.629 92.195,66.629 v1(96.806,62.024)
UART3_TX: J4.3 U3.29 | length 34.1
  Top w0.15: U3.29 71.411,67.639 72.143,67.639 73.137,66.644 v1(75.952,66.681) 76.039,66.532 76.039,65.978 80.329,61.688 93.893,61.687 97.547,61.683 J4.3
V3_3: C7.1 C10.1 C11.1 C12.1 C13.1 C14.1 C17.1 C30.1 C31.1 C32.1 C33.1 C34.1 FB1.1 J2.1 J3.1 J4.1 J5.1 J6.1 J11.1 R3.1 R10.1 R20.1 R21.1 R22.1 R23.1 R24.1 R25.1 R26.1 R27.1 R29.1 R34.1 SW3.3 U2.5 U3.1 U3.19 U3.32 U3.48 U3.64 U4.8 U5.8 U6.9 U7.3 | length 319.5
  Top w0.15: C31.1 29.775,59.41 J5.1 33.835,51.1 R24.1 35.482,50.393 35.568,50.393 38.068,50.393 R25.1 ; v1(33,77.2) 33.037,77.163 33.104,77.163 34.196,76.072 v1(35.151,76.065) 35.217,76.006 35.248,76.006 36.654,74.6 R20.1 ; U4.8@33.59,77.2 U4.8 ; U5.8 34.754,67.671 34.754,67.105 36.259,65.6 R22.1 39.917,66.742 39.998,66.742 41.633,66.742 R23.1 42.775,63.821 44.259,62.337 44.259,62.238 v1(44.285,62.212) 44.285,61.546 45.05,60.781 v1(45.084,60.747) 45.203,60.747 SW3.3 ; R21.1@42.6,74.4 42.775,74.575 R21.1 ; C7.1@45.587,92.567 44.123,92.567 v1(44.123,93.716) 46.588,93.716 48.633,91.671 v1(48.684,91.62) 48.73,91.62 U2.5 50.513,89.837 51.367,89.837 56.316,84.889 56.316,82.721 57.137,81.9 R3.1 ; C12.1 53.752,60.473 53.837,60.473 58.223,60.473 U3.64 ; U3.1 59.4,59.4 U3.64 ; R10.1 67.299,45.676 v1(69.141,45.676) 69.253,45.564 v1(69.972,45.564) 70.336,45.2 R34.1 ; U3.32 70.311,70.239 v1(70.299,70.239) 69.159,71.379 v1(61.135,71.379) 61.157,71.4 U3.48 61.65,66.464 61.074,65.889 61.074,65.879 v1(60.941,65.746) 60.941,62.276 60.533,61.868 60.533,61.829 v1(60.479,61.775) 60.354,61.65 U3.64 ; U3.19 C10.1 76.575,62.155 76.932,61.798 76.932,61.723 v1(76.991,61.664) 77.277,61.378 82.609,61.378 82.612,61.378 J11.1 ; U3.32 C11.1 ; R27.1 85.47,96.105 v1(85.47,95.291) ; v1(86.816,95.224) 87.279,94.761 92.959,94.761 95.581,92.149 U6.9 95.575,87.908 94.776,87.109 94.784,76.442 J2.1
  Top w0.3: C13.1 61.65,76.575 ; U3.1@61.5,59.4 U3.1 ; U3.48 61.65,71.494 61.65,71.587 61.65,71.681 61.65,71.775 61.65,71.869 61.65,71.963 U3.48@61.65,72.056
  Top w0.364: 100.03,96.8 C33.1
  Top w0.375: R25.1 42.628,47.247 v1(42.628,46.259) v1@42.674,46.213 ; U7.3@42.335,37.865 43,37.2 C34.1 ; v1@42.674,46.213 43.871,45.016 v1(44.176,45.015) 46.875,42.315 R29.1 ; C17.1 60.575,59.4 61.5,59.4 ; U3.48@61.65,72.056 61.65,72.15 61.65,76.575 ; U6.9 95.575,92.345 100.03,96.8
  Top w0.38: 33.997,68.44 34.103,68.334 34.121,68.316 34.209,68.228 34.315,68.122 34.421,68.016 34.527,67.91 U5.8@34.625,67.812 ; U5.8@34.435,67.8 U5.8
  Top w0.392: 33.891,68.546 33.997,68.44
  Top w0.4: U7.3@42.335,37.865 U7.3
  Top w0.461: 33.785,68.652 33.891,68.546
  Top w0.531: v1@32.689,69.748 33.785,68.652
  Top w0.568: U4.8@33.411,77.305 U4.8
  Top w0.6: C31.1 31.975,67.8 U5.8@34.435,67.8 ; C30.1 29.775,77.305 U4.8@33.411,77.305 ; v1(32.6,69.8) 32.652,69.748 v1@32.689,69.748 ; v1(33,77.2) U4.8@33.59,77.2 ; U5.8 U5.8@34.625,67.812 ; v1(38.103,73.738) 38.103,73.928 R20.1 38.7,74.675 38.7,74.4 39.6,73.5 41.1,73.5 42,74.4 R21.1@42.6,74.4 ; SW3.3 50.475,59.55 C12.1 ; C34.1 R29.1 ; R3.1 57.475,80.75 C13.1 ; C17.1 55.2,54.025 FB1.1 55.2,50.488 v1(57.957,50.488) 58.032,50.413 58.032,50.408 58.787,49.653 v1(63.915,49.649) 63.936,49.632 63.936,49.592 64.075,49.453 R10.1 ; C10.1 C14.1 C11.1 ; J6.1 83.6,100.8 R26.1 R27.1 ; J11.1 83.673,60.32 85.905,58.088 J4.1 ; J3.1 J2.1 ; C33.1 102.775,97.305 102.602,97.478 102.602,97.48 v1(102.592,97.49) 102.592,98.638 102.664,98.709 102.664,98.78 v1(102.722,98.838) 102.722,100.747 C32.1
  Bottom w0.15: v1(85.47,95.291) 85.49,95.271 85.584,95.271 85.629,95.226 v1(86.816,95.224) ; J4.1 J3.1
  Bottom w0.6: v1(32.6,69.8) 34.165,69.8 v1(38.103,73.738)
V5: C4.1 C5.1 C6.1 J9.1 J9.2 J9.3 J9.4 J9.5 J9.6 L1.2 R2.1 R4.1 R32.1 U2.1 U2.3 | length 137.6
  Top w0.15: v1(43.8,94.6) R4.1@45.075,95.875 ; C6.1 46.482,85.893 v1(46.482,83.129) ; v1(46.621,91.987) 46.621,91.529 U2.1 ; v1(47.464,82.814) 48.561,82.814 R2.1 ; 49.475,82.432 v1(49.242,82.665) 55.143,76.764 55.143,64.611 55.143,64.561 v1(55.158,64.546) 55.158,56.741 61.075,50.926 61.085,47.086 61.929,46.129 61.929,46.123 v1(61.944,46.108) 61.944,45.331 R32.1 61.404,45.2 v1(61.38,45.224) 75.224,45.223 J9.1
  Top w0.475: U2.1 49.265,88.715 v1(48.769,88.715) 48.891,88.593 v1(51.838,88.593) 51.631,88.8 U2.3 51.457,88.593 v1(51.8,88.275) 51.866,88.621 51.866,88.653 56.6,93.387 v1(56.6,96.6) 56.606,96.594 56.8,96.4 C5.1
  Top w0.6: 45.475,88.8 49.05,88.8
  Top w0.8: R4.1@45.075,95.875 R4.1 ; C6.1 45.475,88.8 ; U2.1@49.05,88.8 U2.1 ; R2.1 49.475,82.432 ; C4.1 57.9,99.112 L1.2 58.275,97.525 C5.1 ; J9.1 J9.2 J9.3 J9.4 ; J9.5 J9.6
  Bottom w0.15: v1(43.8,94.6) 44.097,94.6 46.538,92.159 46.538,92.07 v1(46.621,91.987) ; v1(46.482,83.129) 46.557,83.054 46.564,83.054 46.804,82.814 v1(47.464,82.814)
  Bottom w0.8: J9.4 J9.5
V12: C1.1 C2.1 R1.1 R30.1 SW1.1 U1.4 U1.5 | length 83
  Top w0.15: U1.5 52.605,97.9 v1(52.971,98.266) ; v1(53.187,99.74) 53.255,99.808 53.255,99.841 53.475,100.062 C2.1
  Top w0.475: R1.1 42.364,82.789 v1(43.61,82.789) v1@43.619,82.798 ; 43.619,85.222 v1(52.333,93.936) C1.1@53.388,94.991
  Top w0.532: U1.5@51.449,97.634 U1.5 ; U1.4@51.737,96.95 C1.1
  Top w0.8: SW1.1 34.8,81.9 R1.1 41.475,80.542 v1(42.175,79.842) ; v1@43.619,82.798 43.619,85.222 ; v1(51.276,48.167) 51.349,48.094 52.075,47.368 R30.1 ; U1.5@51.449,97.634 51.449,97.216 U1.4 U1.4@51.737,96.95 ; C1.1@53.388,94.991 C1.1
  Bottom w0.15: v1(52.971,98.266) 53.015,98.31 53.015,98.312 53.187,98.484 v1(53.187,99.74)
  Bottom w0.8: v1(42.175,79.842) 42.212,79.805 42.212,79.661 51.276,70.597 v1(51.276,48.167)
V12_IN: J1.1 SW1.2 | length 13.6
  Top w0.25: J1.1 31.8,99.4 SW1.2
VDDA: C15.1 C16.1 FB1.2 U3.13 | length 22.2
  Top w0.15: U3.13 67.633,57.402 v1(66.696,56.448) 66.71,56.462 67.015,56.157 v1(69.282,56.157) 69.25,56.189 69.25,56.292 70.075,57.117 C16.1
  Top w0.25: FB1.2 57.27,53.07 v1(57.27,53.279) ; v1(65.144,56.314) 65.178,56.348 66.03,57.2 C15.1 67.65,58.275 U3.13
  Bottom w0.25: v1(57.27,53.279) 57.381,53.39 57.381,53.408 58.228,54.255 58.228,54.306 63.136,54.306 v1(65.144,56.314)
pads on no net: J11.6 J11.7 J11.8 SW1.3 SW1.4 SW1.5 SW2.2 SW2.4 SW3.2 SW3.4 U2.4 U3.2 U3.3 U3.4 U3.21 U3.27 U3.50 U3.54 U3.55 U3.56 U3.57 U3.61 U3.62 U5.3 U6.19 U6.20 U7.5 U7.8

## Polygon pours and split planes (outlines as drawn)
GND on Mid1 (solid): 105.1,25.7 25.7,25.7 25.7,86.95 26.5,86.95 26.685,86.968 26.863,87.022 27.028,87.11 27.172,87.228 27.29,87.372 27.378,87.536 27.432,87.715 27.45,87.9 27.432,88.085 27.378,88.264 27.29,88.428 27.172,88.572 27.028,88.69 26.863,88.778 26.685,88.832 26.5,88.85 25.7,88.85 25.7,105.1 105.1,105.1
GND on Bottom (solid): 105,25.8 25.8,25.8 25.8,86.9 26.5,86.9 26.695,86.919 26.883,86.976 27.055,87.069 27.207,87.193 27.331,87.344 27.424,87.517 27.481,87.705 27.5,87.9 27.481,88.095 27.424,88.283 27.331,88.456 27.207,88.607 27.055,88.731 26.883,88.824 26.695,88.881 26.5,88.9 25.8,88.9 25.8,105 105,105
